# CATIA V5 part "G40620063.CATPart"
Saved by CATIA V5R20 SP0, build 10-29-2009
Part number: G40620063
Revision: 11
Definition: design
Nomenclature: G40620063
Source: made
Description: NOT SPECIFIED
Bounding box of the stored display mesh (mm): x -31.5 to 31.5, y -10 to 10, z -20 to 0
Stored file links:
  C:\Users\Raffaele\Desktop\3D X SITO CF\BOLEX\30-GUIDE STRIP REF 406\G40620063.CATPart
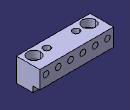
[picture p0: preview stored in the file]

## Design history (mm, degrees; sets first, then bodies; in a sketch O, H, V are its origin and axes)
Body1 "MANIFOLD_SOLID_BREP #1816" (main body)
  Solid1: solid without history
Body2 "MANIFOLD_SOLID_BREP #1954"
  Solid2: solid without history
Body3 "MANIFOLD_SOLID_BREP #2066"
  Solid3: solid without history
Body4 "MANIFOLD_SOLID_BREP #2178"
  Solid4: solid without history
Body5 "MANIFOLD_SOLID_BREP #2290"
  Solid5: solid without history
Body6 "MANIFOLD_SOLID_BREP #2402"
  Solid6: solid without history
Body7 "MANIFOLD_SOLID_BREP #2514"
  Solid7: solid without history
Body8 "MANIFOLD_SOLID_BREP #2626"
  Solid8: solid without history
Body9 "MANIFOLD_SOLID_BREP #2764"
  Solid9: solid without history
Body10 "MANIFOLD_SOLID_BREP #2902"
  Solid10: solid without history
Body11 "MANIFOLD_SOLID_BREP #3040"
  Solid11: solid without history
Body12 "MANIFOLD_SOLID_BREP #3178"
  Solid12: solid without history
